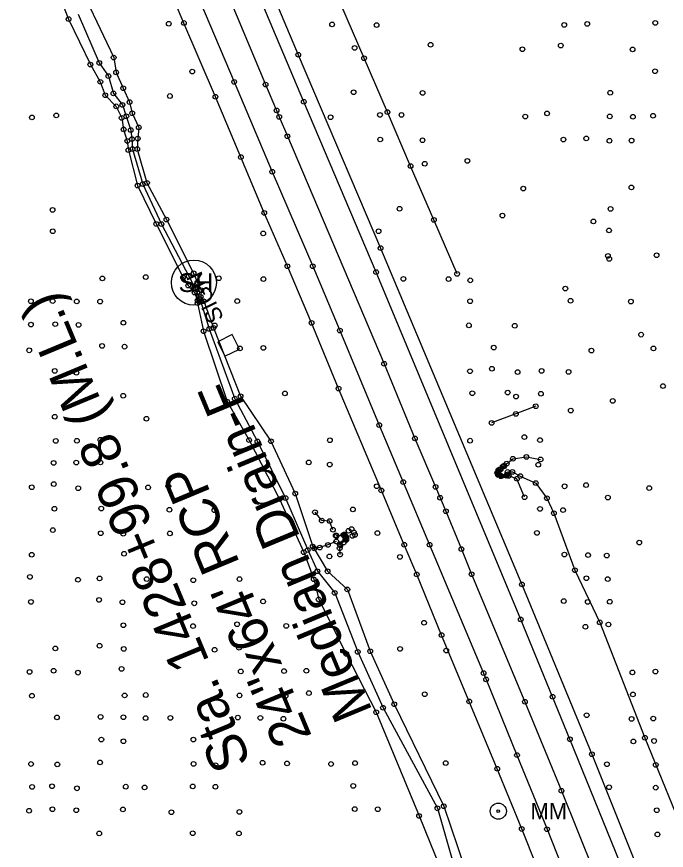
# Model space of a CAD drawing. Extents: x 20503438 to 20508873, y 7964251 to 7984667.
# Drawn here: x 20506022.2 to 20506298.8, y 7975470.8 to 7975825.9 of the extents above; entities that cross this region are included whole.
import ezdxf

# ---------------------------------------------------------------- set-up
doc = ezdxf.new("R2010")
doc.units = 0
for name, color, linetype in [('SurBreakLine', 7, 'Continuous'), ('SurConcreteSlab', 7, 'Continuous'), ('SurDikeDam', 7, 'Continuous'), ('SurDrainageArrowDown', 7, 'Continuous'), ('SurDrainageArrowUp', 7, 'Continuous'), ('SurEdgeRoadPaved', 7, 'Continuous'), ('SurEdgeShoulderPaved', 7, 'Continuous'), ('SurNaturalCells', 7, 'Continuous'), ('SurPointsNonDTM', 7, 'Continuous'), ('SurRoadPoints', 7, 'Continuous'), ('SurSurveyPoints', 7, 'Continuous'), ('SurTxtDrainage', 7, 'Continuous')]:
    doc.layers.add(name, color=color, linetype=linetype)

msp = doc.modelspace()

# ---------------------------------------------------------------- linework, layer by layer
at = {"layer": 'SurBreakLine'}
for points in [[(20506035.97, 7975845.81), (20506044.28, 7975824.82), (20506053.54, 7975805.46), (20506057.79, 7975798.12), (20506059.91, 7975792.38), (20506064.6, 7975787.68), (20506066.88, 7975782.77), (20506067.72, 7975777.87), (20506069.28, 7975772.92), (20506069.74, 7975769.07), (20506073.62, 7975753.93), (20506081.58, 7975737.59), (20506093.02, 7975714.8), (20506095.2, 7975711.32), (20506097.9, 7975708.34), (20506099.2, 7975704.94), (20506099.2, 7975703.86), (20506101.75, 7975691.91), (20506111.73, 7975661.94), (20506121.13, 7975645.52), (20506134.06, 7975620.43), (20506144.37, 7975597.78), (20506148.64, 7975586.25), (20506150.75, 7975577.71), (20506162.51, 7975554.47), (20506175.24, 7975529.63), (20506193.49, 7975485.46), (20506211.46, 7975441.43)], [(20506053.38, 7975829.85), (20506063.47, 7975808.48), (20506064.52, 7975802.14), (20506067.56, 7975795.42), (20506070.22, 7975789.47), (20506071.37, 7975784.76), (20506074.15, 7975778.72), (20506073.69, 7975773.96), (20506073.53, 7975769.51), (20506077.66, 7975755.1), (20506085.93, 7975739.46), (20506097.46, 7975716.57), (20506099.15, 7975712.59), (20506100.78, 7975709.34), (20506100.54, 7975706.51), (20506101.82, 7975704.66), (20506105.97, 7975693.34), (20506117.47, 7975664.18), (20506130.45, 7975645.04), (20506140.79, 7975622.73), (20506148.26, 7975600.18), (20506154.52, 7975589.65), (20506162.95, 7975581.92), (20506172.7, 7975555.61), (20506182.93, 7975533.02), (20506204.02, 7975489.57), (20506218.94, 7975445.66)], [(20506113.52, 7975831.94), (20506128.17, 7975796.98), (20506132.8, 7975785.96), (20506133.96, 7975783.2), (20506137.43, 7975774.93), (20506178.6, 7975678.04), (20506191.71, 7975646.27), (20506200.51, 7975625.58), (20506204.91, 7975615.23), (20506211.49, 7975599.14), (20506215.87, 7975588.4), (20506238.54, 7975534.12), (20506254.12, 7975496.18), (20506268.1, 7975461.5)], [(20506238.4, 7975621.2), (20506235.15, 7975629.05), (20506231.64, 7975630.28), (20506230.62, 7975630.33), (20506228.33, 7975630.14), (20506227.16, 7975630.67), (20506226.74, 7975631.61), (20506227.27, 7975632.74), (20506229.1, 7975634.26), (20506229.68, 7975634.69), (20506230.84, 7975635.52), (20506233.42, 7975637.57), (20506239.21, 7975638.37), (20506245.2, 7975637.29)], [(20506156.82, 7975607.37), (20506155.41, 7975611.05), (20506152.03, 7975611.29), (20506149.19, 7975614.82)], [(20506159.86, 7975596.78), (20506159.69, 7975599.5), (20506159.95, 7975600.7)]]:
    msp.add_lwpolyline(points, dxfattribs=at)
at = {"layer": 'SurConcreteSlab'}
for points in [[(20506229.68, 7975634.36), (20506228.19, 7975633.02), (20506227.26, 7975632.12), (20506227.16, 7975632.01), (20506227.04, 7975631.43), (20506227.41, 7975630.85), (20506228.07, 7975630.59), (20506230.99, 7975630.82), (20506230.74, 7975630.4), (20506228.52, 7975630.21), (20506227.19, 7975630.88), (20506227.05, 7975631.17), (20506226.95, 7975631.91), (20506227.84, 7975633.06), (20506229.21, 7975634.31)], [(20506159.63, 7975601.24), (20506162.23, 7975603.47), (20506162.2, 7975604.05), (20506161.96, 7975604.47), (20506161.5, 7975604.84), (20506158.33, 7975604.56), (20506158.32, 7975604.9), (20506161.29, 7975605.17), (20506162.09, 7975604.76), (20506162.34, 7975604.34), (20506162.48, 7975603.77), (20506162.22, 7975603.09), (20506159.88, 7975600.87)]]:
    msp.add_lwpolyline(points, close=True, dxfattribs=at)
at = {"layer": 'SurDikeDam'}
msp.add_lwpolyline([(20506243.18, 7975659.95), (20506234.69, 7975656.72), (20506224.39, 7975652.83)], dxfattribs=at)
at = {"layer": 'SurDrainageArrowDown'}
for points in [[(20506209.68, 7975716.34), (20506199.78, 7975739.3), (20506189.89, 7975762.26), (20506179.99, 7975785.21), (20506170.1, 7975808.17), (20506160.2, 7975831.13), (20506150.31, 7975854.09), (20506140.42, 7975877.04), (20506130.52, 7975900), (20506120.64, 7975922.97), (20506110.83, 7975945.96), (20506101.02, 7975968.95), (20506091.21, 7975991.95), (20506081.4, 7976014.94), (20506071.59, 7976037.93), (20506061.78, 7976060.93), (20506052.23, 7976084.03), (20506042.81, 7976107.19), (20506033.39, 7976130.35), (20506023.98, 7976153.51), (20506014.56, 7976176.66), (20506014.08, 7976177.84)], [(20506158.24, 7975602.36), (20506154.69, 7975600.89), (20506151.22, 7975599.78), (20506148.89, 7975599.39)]]:
    msp.add_lwpolyline(points, dxfattribs=at)
at = {"layer": 'SurDrainageArrowUp'}
for points in [[(20506048.33, 7975826.92), (20506057.34, 7975806.17), (20506061.24, 7975800.56), (20506063.39, 7975793.17), (20506067.19, 7975788.32), (20506068.86, 7975783.46), (20506070.76, 7975777.57), (20506071.25, 7975773.73), (20506071.49, 7975769.47), (20506075.87, 7975754.6), (20506083.83, 7975737.53), (20506095.45, 7975715.32), (20506098.07, 7975710.44), (20506099.08, 7975708.35), (20506099.83, 7975705.65), (20506100.53, 7975704.36), (20506104.15, 7975692.87), (20506115.04, 7975663.18), (20506124.67, 7975644.95), (20506136.63, 7975620.82), (20506146.08, 7975598.73), (20506150.21, 7975589.66), (20506157.56, 7975580.45), (20506167.38, 7975555.34), (20506178.14, 7975531.57), (20506201.29, 7975488.71), (20506214.15, 7975443.99)], [(20506231.15, 7975631.95), (20506233.26, 7975631.96), (20506236.58, 7975630.18), (20506243.17, 7975627.24), (20506247.93, 7975620.78), (20506250.89, 7975614.39), (20506259.85, 7975590.11), (20506270.44, 7975567.92), (20506289.62, 7975518.74), (20506308.54, 7975472.45)]]:
    msp.add_lwpolyline(points, dxfattribs=at)
at = {"layer": 'SurEdgeRoadPaved'}
for points in [[(20506278.91, 7975465.84), (20506257.71, 7975518.12), (20506250.34, 7975536.21), (20506236.76, 7975569.18), (20506175.22, 7975717.06), (20506144.4, 7975789.63), (20506112.25, 7975866.01), (20506069.58, 7975966.38), (20506037.98, 7976041.41), (20506015.97, 7976094.11), (20505947.59, 7976255.69), (20505927.83, 7976303), (20505916.28, 7976330.64), (20505901.17, 7976367.49), (20505888.02, 7976400.52), (20505875.61, 7976430.87)], [(20506255.81, 7975433.25), (20506237.19, 7975479.91), (20506226.78, 7975505.57), (20506214.87, 7975534.22), (20506203.08, 7975562.49), (20506192.5, 7975588.31), (20506187.17, 7975600.94), (20506177.43, 7975624.08), (20506159.21, 7975667.51), (20506147.71, 7975695.43), (20506137.43, 7975719.56), (20506127.59, 7975742.28), (20506117.61, 7975766.06), (20506106.77, 7975791.77), (20506093.39, 7975823.17), (20506078.53, 7975858.38)], [(20506092.07, 7975851.84), (20506114.77, 7975798.09), (20506130.95, 7975759.82), (20506148.22, 7975719.61), (20506159.79, 7975692.2), (20506176.52, 7975651.95), (20506186.76, 7975627.64), (20506197.99, 7975600.97), (20506220.93, 7975546.31), (20506222.03, 7975543.62), (20506235.18, 7975511.38), (20506247.96, 7975479.81), (20506260.54, 7975448.2)]]:
    msp.add_lwpolyline(points, dxfattribs=at)
at = {"layer": 'SurEdgeShoulderPaved'}
msp.add_lwpolyline([(20505889.98, 7976411.65), (20505895.55, 7976397.9), (20505920.61, 7976336.44), (20505950.34, 7976264.44), (20506010.6, 7976121.59), (20506025.61, 7976085.79), (20506040.8, 7976049.02), (20506074.56, 7975969.59), (20506097.02, 7975916.55), (20506142.06, 7975809.67), (20506177.13, 7975727.28), (20506237.29, 7975584.09), (20506267.06, 7975511.74), (20506296.53, 7975437.96)], dxfattribs=at)
at = {"layer": 'SurNaturalCells'}
msp.add_circle((20506097.63, 7975712.61), 9.59, dxfattribs=at)
at = {"layer": 'SurPointsNonDTM'}
msp.add_circle((20506202.46, 7975620.99), 1, dxfattribs=at)
at = {"layer": 'SurRoadPoints'}
msp.add_lwpolyline([(20506115.47, 7975687.4), (20506115.47, 7975687.4), (20506113.96, 7975690.47), (20506107.81, 7975687.44), (20506110.84, 7975681.29), (20506116.99, 7975684.32), (20506115.47, 7975687.39)], dxfattribs=at)
for radius in [3.43, 0.571]:
    msp.add_circle((20506227.22, 7975487.5), radius, dxfattribs=at)
at = {"layer": 'SurSurveyPoints'}
for centre in [(20506044.28, 7975824.82), (20506086.95, 7975822.87), (20506093.39, 7975823.17), (20506156.48, 7975822.58), (20506175.42, 7975822.31), (20506255.28, 7975822.33), (20506265.06, 7975822.77), (20506294.04, 7975823.24), (20506166.07, 7975812.54), (20506198.4, 7975813.88), (20506237.48, 7975811.98), (20506253.82, 7975813.57), (20506284.41, 7975811.94), (20506063.47, 7975808.48), (20506142.06, 7975809.67), (20506170.1, 7975808.17), (20506053.54, 7975805.46), (20506057.34, 7975806.17), (20506061.24, 7975800.56), (20506064.52, 7975802.14), (20506096.95, 7975802.51), (20506293.95, 7975802.65), (20506057.79, 7975798.12), (20506114.77, 7975798.09), (20506128.17, 7975796.98), (20506063.39, 7975793.17), (20506067.56, 7975795.42), (20506165.62, 7975793.68), (20506195, 7975793.41), (20506274.87, 7975793.45), (20506059.91, 7975792.38), (20506087.39, 7975792.08), (20506106.77, 7975791.77), (20506144.4, 7975789.63), (20506064.6, 7975787.68), (20506067.19, 7975788.32), (20506070.22, 7975789.47), (20506028.68, 7975782.94), (20506039.05, 7975783.81), (20506066.88, 7975782.77), (20506068.86, 7975783.46), (20506071.37, 7975784.76), (20506132.8, 7975785.96), (20506133.96, 7975783.2), (20506155.81, 7975783.02), (20506176.85, 7975784.02), (20506179.99, 7975785.21), (20506186.01, 7975784.01), (20506238.7, 7975783.34), (20506247.99, 7975784.68), (20506274.7, 7975783.38), (20506284.54, 7975783.24), (20506293.1, 7975783.64), (20506067.72, 7975777.87), (20506070.76, 7975777.57), (20506074.15, 7975778.72), (20506069.28, 7975772.92), (20506071.25, 7975773.73), (20506073.69, 7975773.96), (20506137.43, 7975774.93), (20506176.94, 7975773.56), (20506194.95, 7975773.22), (20506254.94, 7975773.55), (20506264.67, 7975774), (20506274.54, 7975773.05), (20506283.95, 7975773.07), (20506069.74, 7975769.07), (20506071.49, 7975769.47), (20506073.53, 7975769.51), (20506117.61, 7975766.06), (20506189.89, 7975762.26), (20506195.91, 7975763.23), (20506214.06, 7975764.43), (20506130.95, 7975759.82), (20506075.87, 7975754.6), (20506077.66, 7975755.1), (20506073.62, 7975753.93), (20506237.85, 7975752.64), (20506283.89, 7975753.14), (20506037.45, 7975743.55), (20506185.17, 7975744.06), (20506275, 7975744), (20506127.59, 7975742.28), (20506228.98, 7975741.13), (20506081.58, 7975737.59), (20506083.83, 7975737.53), (20506085.93, 7975739.46), (20506199.78, 7975739.3), (20506267.74, 7975738.67), (20506037.54, 7975734.48), (20506127.15, 7975733.54), (20506176.22, 7975734.46), (20506274.35, 7975734.85), (20506177.13, 7975727.28), (20506273.89, 7975723.96), (20506274.43, 7975722.73), (20506294.62, 7975724.25), (20506137.43, 7975719.56), (20506148.22, 7975719.61), (20506095.45, 7975715.32), (20506097.46, 7975716.57), (20506175.22, 7975717.06), (20506209.68, 7975716.34), (20506058.65, 7975714.4), (20506077.13, 7975714.98), (20506093.02, 7975714.8), (20506099.15, 7975712.59), (20506108.22, 7975714.45), (20506127.24, 7975714.13), (20506186.81, 7975714.19), (20506206.04, 7975714.13), (20506215.28, 7975713.58), (20506095.2, 7975711.32), (20506097.9, 7975708.34), (20506098.07, 7975710.44), (20506099.08, 7975708.35), (20506100.78, 7975709.34), (20506255.76, 7975710.06), (20506028.21, 7975704.67), (20506037.5, 7975704.73), (20506047.73, 7975704.59), (20506057.7, 7975704.56), (20506099.2, 7975704.94), (20506099.83, 7975705.65), (20506100.54, 7975706.51), (20506101.82, 7975704.66), (20506116.07, 7975704.71), (20506215.22, 7975704.69), (20506257.96, 7975704.85), (20506283.65, 7975704.52), (20506099.2, 7975703.86), (20506100.53, 7975704.36), (20506028.25, 7975694.73), (20506038.61, 7975694.91), (20506048.51, 7975694.6), (20506067.62, 7975695.54), (20506106.53, 7975694.39), (20506147.71, 7975695.43), (20506214.7, 7975694.41), (20506234.23, 7975694.22), (20506101.75, 7975691.91), (20506104.15, 7975692.87), (20506105.97, 7975693.34), (20506159.79, 7975692.2), (20506288.04, 7975690.44), (20506027.51, 7975683.77), (20506058.56, 7975685.63), (20506068.09, 7975685.33), (20506117.21, 7975684.56), (20506127.19, 7975684.77), (20506225.29, 7975684.93), (20506266.89, 7975683.65), (20506293.27, 7975684.58), (20506178.6, 7975678.04), (20506038.42, 7975674.98), (20506047.64, 7975674.22), (20506215.17, 7975674.86), (20506224.47, 7975675.93), (20506235.43, 7975674.51), (20506245.62, 7975674.98), (20506257.13, 7975674.56), (20506136.38, 7975665.42), (20506159.21, 7975667.51), (20506216.16, 7975665.49), (20506231.21, 7975665.76), (20506297.34, 7975668.54), (20506067.52, 7975664.42), (20506111.73, 7975661.94), (20506115.04, 7975663.18), (20506117.47, 7975664.18), (20506234.79, 7975664.05), (20506245.33, 7975665.28), (20506275.92, 7975662.23), (20506243.18, 7975659.95), (20506038.41, 7975655.48), (20506234.69, 7975656.72), (20506258.07, 7975658.14), (20506077.44, 7975654.64), (20506176.52, 7975651.95), (20506224.39, 7975652.83), (20506038.82, 7975645.22), (20506047.82, 7975645.23), (20506057.86, 7975645.68), (20506121.13, 7975645.52), (20506124.67, 7975644.95), (20506130.45, 7975645.04), (20506155.52, 7975645.46), (20506191.71, 7975646.27), (20506215.23, 7975645.29), (20506238.32, 7975646.79), (20506244.98, 7975645.53), (20506233.42, 7975637.57), (20506239.21, 7975638.37), (20506245.2, 7975637.29), (20506037.92, 7975635.8), (20506047.56, 7975635.99), (20506057.82, 7975636.01), (20506146.54, 7975636.03), (20506155.45, 7975635.13), (20506229.1, 7975634.26), (20506229.21, 7975634.31), (20506229.68, 7975634.69), (20506229.68, 7975634.36), (20506230.84, 7975635.52), (20506244.25, 7975635.06), (20506226.74, 7975631.61), (20506226.95, 7975631.91), (20506227.04, 7975631.43), (20506227.05, 7975631.17), (20506227.16, 7975632.01), (20506227.16, 7975630.67), (20506227.19, 7975630.88), (20506227.26, 7975632.12), (20506227.27, 7975632.74), (20506227.41, 7975630.85), (20506227.84, 7975633.06), (20506228.07, 7975630.59), (20506228.19, 7975633.02), (20506228.33, 7975630.14), (20506228.52, 7975630.21), (20506230.62, 7975630.33), (20506230.74, 7975630.4), (20506230.99, 7975630.82), (20506231.15, 7975631.95), (20506231.64, 7975630.28), (20506233.26, 7975631.96), (20506236.58, 7975630.18), (20506037.97, 7975626.82), (20506186.76, 7975627.64), (20506235.15, 7975629.05), (20506243.17, 7975627.24), (20506264.6, 7975626.4), (20506028.62, 7975625.45), (20506048.38, 7975625.04), (20506078.13, 7975625.36), (20506086.74, 7975625.89), (20506140.79, 7975622.73), (20506175.47, 7975625.86), (20506177.43, 7975624.08), (20506200.51, 7975625.58), (20506255.42, 7975625.85), (20506291.46, 7975625.08), (20506134.06, 7975620.43), (20506136.63, 7975620.82), (20506238.4, 7975621.2), (20506247.93, 7975620.78), (20506273.87, 7975621.07), (20506038.26, 7975616.32), (20506058.2, 7975616.4), (20506087.23, 7975615.87), (20506106.37, 7975615.66), (20506165.32, 7975616.04), (20506244.98, 7975616.23), (20506254.78, 7975615.7), (20506149.19, 7975614.82), (20506204.91, 7975615.23), (20506250.89, 7975614.39), (20506152.03, 7975611.29), (20506155.41, 7975611.05), (20506037.57, 7975607.2), (20506057.95, 7975605.84), (20506067.55, 7975605.62), (20506087.4, 7975605.82), (20506156.82, 7975607.37), (20506158.03, 7975604.97), (20506161.29, 7975605.17), (20506161.69, 7975605.39), (20506163.45, 7975606.95), (20506164.75, 7975607.63), (20506165.78, 7975606.21), (20506166.16, 7975605.15), (20506175.78, 7975605.92), (20506243.67, 7975606.01), (20506158.24, 7975602.36), (20506158.32, 7975604.9), (20506158.33, 7975604.56), (20506161.42, 7975601.91), (20506161.5, 7975604.84), (20506161.96, 7975604.47), (20506162.09, 7975604.76), (20506162.2, 7975604.05), (20506162.22, 7975603.09), (20506162.23, 7975603.47), (20506162.34, 7975604.34), (20506162.48, 7975603.77), (20506162.48, 7975603.03), (20506165.1, 7975604.76), (20506287.25, 7975601.86), (20506146.08, 7975598.73), (20506148.26, 7975600.18), (20506148.89, 7975599.39), (20506151.22, 7975599.78), (20506154.69, 7975600.89), (20506159.63, 7975601.24), (20506159.69, 7975599.5), (20506159.88, 7975600.87), (20506159.95, 7975600.7), (20506187.17, 7975600.94), (20506197.99, 7975600.97), (20506211.49, 7975599.14), (20506028.58, 7975596.71), (20506067.91, 7975597.14), (20506144.37, 7975597.78), (20506155.33, 7975595.97), (20506159.86, 7975596.78), (20506185.33, 7975595.77), (20506255.36, 7975596.79), (20506265.42, 7975596.55), (20506273.4, 7975596.37), (20506027.84, 7975587.28), (20506150.21, 7975589.66), (20506154.52, 7975589.65), (20506192.5, 7975588.31), (20506215.87, 7975588.4), (20506259.85, 7975590.11), (20506048.28, 7975586.05), (20506057.45, 7975586.61), (20506077.57, 7975586.36), (20506097.37, 7975585.86), (20506117.04, 7975586.33), (20506148.64, 7975586.25), (20506237.29, 7975584.09), (20506264.71, 7975586.68), (20506273.81, 7975586.34), (20506157.56, 7975580.45), (20506162.95, 7975581.92), (20506028.27, 7975576.61), (20506057.26, 7975577.45), (20506127.09, 7975576.83), (20506150.75, 7975577.71), (20506255.09, 7975576.98), (20506265.28, 7975576.61), (20506274.68, 7975576.7), (20506067.21, 7975576.5), (20506097.78, 7975576.02), (20506067.62, 7975566.66), (20506097.26, 7975566.3), (20506116.04, 7975567.08), (20506136.91, 7975566.43), (20506195.6, 7975567.74), (20506236.76, 7975569.18), (20506264.32, 7975566.01), (20506270.44, 7975567.92), (20506274.13, 7975567), (20506203.08, 7975562.49), (20506038.64, 7975556.83), (20506057.47, 7975557.94), (20506067.78, 7975556.58), (20506106.44, 7975556.22), (20506116.84, 7975557.08), (20506167.38, 7975555.34), (20506172.7, 7975555.61), (20506185.4, 7975556.62), (20506205.08, 7975555.91), (20506162.51, 7975554.47), (20506027.65, 7975546.8), (20506037.92, 7975547.33), (20506048.25, 7975546.49), (20506066.81, 7975548.11), (20506117.6, 7975546.99), (20506136, 7975547.14), (20506145.5, 7975547.27), (20506220.93, 7975546.31), (20506284.35, 7975546.6), (20506294.12, 7975546.95), (20506222.03, 7975543.62), (20506146.58, 7975537.77), (20506028.68, 7975536.64), (20506068.15, 7975536.78), (20506077.13, 7975536.97), (20506117.04, 7975536.77), (20506136.68, 7975536.55), (20506195.89, 7975537.32), (20506214.87, 7975534.22), (20506238.54, 7975534.12), (20506250.34, 7975536.21), (20506284.55, 7975537.2), (20506178.14, 7975531.57), (20506182.93, 7975533.02), (20506039.31, 7975527.45), (20506057.88, 7975527.66), (20506067.6, 7975527.53), (20506077.08, 7975527.15), (20506087.63, 7975527.22), (20506116.33, 7975527.39), (20506125.91, 7975527.22), (20506135.77, 7975526.87), (20506175.24, 7975529.63), (20506264.84, 7975528.38), (20506293.21, 7975526.96), (20506283.94, 7975526.77), (20506058.22, 7975517.99), (20506067.63, 7975517.27), (20506097.4, 7975517.96), (20506257.71, 7975518.12), (20506284.72, 7975517.23), (20506289.62, 7975518.74), (20506293.57, 7975517.39), (20506235.18, 7975511.38), (20506267.06, 7975511.74), (20506028.3, 7975507.59), (20506039.48, 7975507.44), (20506057.68, 7975508.28), (20506097.46, 7975507.63), (20506106.84, 7975507.09), (20506126.86, 7975508.15), (20506137.29, 7975507.83), (20506156.03, 7975507.59), (20506166.22, 7975507.99), (20506204.82, 7975507.99), (20506226.78, 7975505.57), (20506273.49, 7975507.51), (20506294.24, 7975507.21), (20506028.77, 7975497.86), (20506037.24, 7975498.1), (20506047.85, 7975497.23), (20506068.64, 7975497.93), (20506076.66, 7975497.6), (20506097.17, 7975498.06), (20506106.81, 7975497.9), (20506165.46, 7975498.26), (20506254.12, 7975496.18), (20506274.4, 7975497.71), (20506294.25, 7975497.51), (20506037.4, 7975488.29), (20506047.55, 7975487.88), (20506067.43, 7975488.22), (20506166.11, 7975488.4), (20506175.93, 7975488.32), (20506201.29, 7975488.71), (20506204.02, 7975489.57), (20506294.68, 7975487.87), (20506027.48, 7975487.66), (20506088.05, 7975487.07), (20506117, 7975487.2), (20506193.49, 7975485.46), (20506057.3, 7975478), (20506097.13, 7975478.12), (20506116.82, 7975478.02), (20506237.19, 7975479.91), (20506247.96, 7975479.81), (20506294.98, 7975477.58)]:
    msp.add_circle(centre, 1, dxfattribs=at)

# ---------------------------------------------------------------- texts
at = {"layer": 'SurNaturalCells'}
msp.add_text('SH', height=7.995, rotation=360, dxfattribs=at).set_placement((20506091.11, 7975708.61))
at = {"layer": 'SurRoadPoints'}
for s, rotation, p in [('SIGN', 116.2291, (20506110.58, 7975697.48)), ('MM', 360, (20506240.93, 7975484.01))]:
    msp.add_text(s, height=6.995, rotation=rotation, dxfattribs=at).set_placement(p)
at = {"layer": 'SurTxtDrainage'}
for s, p in [('Sta. 1428+99.8 (M.L.)', (20506122.14, 7975508.61)), ('Median Drain-F', (20506173.84, 7975530.11)), ('24"x64\' RCP', (20506147.99, 7975519.36))]:
    msp.add_text(s, height=16.8, rotation=112.5788, dxfattribs=at).set_placement(p)

doc.saveas('drawing.dxf')
